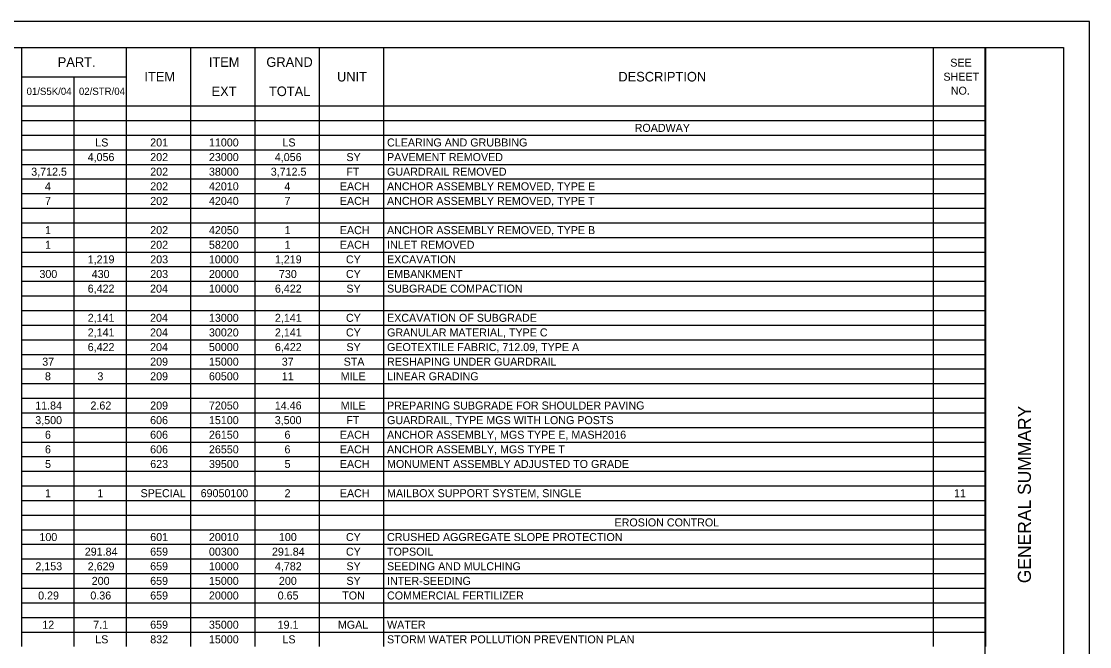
# Model space of a CAD drawing. Extents: x 0 to 34, y 0 to 22.
# Drawn here: x 13.53 to 34, y 10.02 to 22 of the extents above; entities that cross this region are included whole.
import ezdxf

# ---------------------------------------------------------------- set-up
doc = ezdxf.new("R2010")
doc.units = 0
for name, color, linetype in [('SH_Border', 7, 'Continuous'), ('SH_Cut_Line', 7, 'Continuous'), ('SH_Data', 7, 'Continuous'), ('SH_Text', 7, 'Continuous')]:
    doc.layers.add(name, color=color, linetype=linetype)

msp = doc.modelspace()

# ---------------------------------------------------------------- linework, layer by layer
at = {"layer": 'SH_Border'}
msp.add_line((32, 0.5), (32, 21.5), dxfattribs=at)
msp.add_lwpolyline([(1.5, 21.5), (33.5, 21.5), (33.5, 0.5), (1.5, 0.5)], close=True, dxfattribs=at)
at = {"layer": 'SH_Cut_Line'}
msp.add_lwpolyline([(0, 0), (34, 0), (34, 22), (0, 22)], close=True, dxfattribs=at)
at = {"layer": 'SH_Text'}
for p, q in [((13.532, 21.5), (15.537, 21.5)), ((13.532, 21.5), (13.532, 21.22)), ((15.537, 21.5), (32.004, 21.5)), ((15.537, 21.5), (15.537, 21.22)), ((16.771, 21.5), (16.771, 21.22)), ((18.005, 21.5), (18.005, 21.22)), ((19.239, 21.5), (19.239, 21.22)), ((20.473, 21.5), (20.473, 21.22)), ((31.001, 21.5), (31.001, 21.22)), ((32.004, 21.5), (32.004, 21.22)), ((13.532, 21.22), (13.532, 20.94)), ((15.537, 21.22), (15.537, 20.94)), ((16.771, 21.22), (16.771, 20.94)), ((18.005, 21.22), (18.005, 20.94)), ((19.239, 21.22), (19.239, 20.94)), ((20.473, 21.22), (20.473, 20.94)), ((31.001, 21.22), (31.001, 20.94)), ((32.004, 21.22), (32.004, 20.94)), ((13.532, 20.94), (15.537, 20.94)), ((13.532, 20.94), (13.532, 20.66)), ((14.535, 20.94), (14.535, 20.66)), ((15.537, 20.94), (15.537, 20.66)), ((16.771, 20.94), (16.771, 20.66)), ((18.005, 20.94), (18.005, 20.66)), ((19.239, 20.94), (19.239, 20.66)), ((20.473, 20.94), (20.473, 20.66)), ((31.001, 20.94), (31.001, 20.66)), ((32.004, 20.94), (32.004, 20.66)), ((13.532, 20.66), (13.532, 20.38)), ((14.535, 20.66), (14.535, 20.38)), ((15.537, 20.66), (15.537, 20.38)), ((16.771, 20.66), (16.771, 20.38)), ((18.005, 20.66), (18.005, 20.38)), ((19.239, 20.66), (19.239, 20.38)), ((20.473, 20.66), (20.473, 20.38)), ((31.001, 20.66), (31.001, 20.38)), ((32.004, 20.66), (32.004, 20.38)), ((13.532, 20.38), (15.537, 20.38)), ((13.532, 20.38), (13.532, 20.1)), ((14.535, 20.38), (14.535, 20.1)), ((15.537, 20.38), (32.004, 20.38)), ((15.537, 20.38), (15.537, 20.1)), ((16.771, 20.38), (16.771, 20.1)), ((18.005, 20.38), (18.005, 20.1)), ((19.239, 20.38), (19.239, 20.1)), ((20.473, 20.38), (20.473, 20.1)), ((31.001, 20.38), (31.001, 20.1)), ((32.004, 20.38), (32.004, 20.1)), ((13.532, 20.1), (15.537, 20.1)), ((13.532, 20.1), (13.532, 18.7)), ((14.535, 20.1), (14.535, 18.7)), ((15.537, 20.1), (32.004, 20.1)), ((15.537, 20.1), (15.537, 18.7)), ((16.771, 20.1), (16.771, 18.7)), ((18.005, 20.1), (18.005, 18.7)), ((19.239, 20.1), (19.239, 18.7)), ((20.473, 20.1), (20.473, 18.7)), ((31.001, 20.1), (31.001, 18.7)), ((32.004, 20.1), (32.004, 18.7)), ((13.532, 19.82), (15.537, 19.82)), ((15.537, 19.82), (32.004, 19.82)), ((13.532, 19.54), (15.537, 19.54)), ((15.537, 19.54), (32.004, 19.54)), ((13.532, 19.26), (15.537, 19.26)), ((15.537, 19.26), (32.004, 19.26)), ((13.532, 18.98), (15.537, 18.98)), ((15.537, 18.98), (32.004, 18.98)), ((13.532, 18.7), (15.537, 18.7)), ((13.532, 18.7), (13.532, 18.14)), ((14.535, 18.7), (14.535, 18.14)), ((15.537, 18.7), (32.004, 18.7)), ((15.537, 18.7), (15.537, 18.14)), ((16.771, 18.7), (16.771, 18.14)), ((18.005, 18.7), (18.005, 18.14)), ((19.239, 18.7), (19.239, 18.14)), ((20.473, 18.7), (20.473, 18.14)), ((31.001, 18.7), (31.001, 18.14)), ((32.004, 18.7), (32.004, 18.14)), ((13.532, 18.42), (15.537, 18.42)), ((15.537, 18.42), (32.004, 18.42)), ((13.532, 18.14), (15.537, 18.14)), ((13.532, 18.14), (13.532, 17.86)), ((14.535, 18.14), (14.535, 17.86)), ((15.537, 18.14), (32.004, 18.14)), ((15.537, 18.14), (15.537, 17.86)), ((16.771, 18.14), (16.771, 17.86)), ((18.005, 18.14), (18.005, 17.86)), ((19.239, 18.14), (19.239, 17.86)), ((20.473, 18.14), (20.473, 17.86)), ((31.001, 18.14), (31.001, 17.86)), ((32.004, 18.14), (32.004, 17.86)), ((13.532, 17.86), (15.537, 17.86)), ((13.532, 17.86), (13.532, 17.58)), ((14.535, 17.86), (14.535, 17.58)), ((15.537, 17.86), (32.004, 17.86)), ((15.537, 17.86), (15.537, 17.58)), ((16.771, 17.86), (16.771, 17.58)), ((18.005, 17.86), (18.005, 17.58)), ((19.239, 17.86), (19.239, 17.58)), ((20.473, 17.86), (20.473, 17.58)), ((31.001, 17.86), (31.001, 17.58)), ((32.004, 17.86), (32.004, 17.58)), ((13.532, 17.58), (15.537, 17.58)), ((13.532, 17.58), (13.532, 17.3)), ((14.535, 17.58), (14.535, 17.3)), ((15.537, 17.58), (32.004, 17.58)), ((15.537, 17.58), (15.537, 17.3)), ((16.771, 17.58), (16.771, 17.3)), ((18.005, 17.58), (18.005, 17.3)), ((19.239, 17.58), (19.239, 17.3)), ((20.473, 17.58), (20.473, 17.3)), ((31.001, 17.58), (31.001, 17.3)), ((32.004, 17.58), (32.004, 17.3)), ((13.532, 17.3), (15.537, 17.3)), ((13.532, 17.3), (13.532, 17.02)), ((14.535, 17.3), (14.535, 17.02)), ((15.537, 17.3), (32.004, 17.3)), ((15.537, 17.3), (15.537, 17.02)), ((16.771, 17.3), (16.771, 17.02)), ((18.005, 17.3), (18.005, 17.02)), ((19.239, 17.3), (19.239, 17.02)), ((20.473, 17.3), (20.473, 17.02)), ((31.001, 17.3), (31.001, 17.02)), ((32.004, 17.3), (32.004, 17.02)), ((13.532, 17.02), (15.537, 17.02)), ((13.532, 17.02), (13.532, 16.74)), ((14.535, 17.02), (14.535, 16.74)), ((15.537, 17.02), (32.004, 17.02)), ((15.537, 17.02), (15.537, 16.74)), ((16.771, 17.02), (16.771, 16.74)), ((18.005, 17.02), (18.005, 16.74)), ((19.239, 17.02), (19.239, 16.74)), ((20.473, 17.02), (20.473, 16.74)), ((31.001, 17.02), (31.001, 16.74)), ((32.004, 17.02), (32.004, 16.74)), ((13.532, 16.74), (15.537, 16.74)), ((13.532, 16.74), (13.532, 16.18)), ((14.535, 16.74), (14.535, 16.18)), ((15.537, 16.74), (32.004, 16.74)), ((15.537, 16.74), (15.537, 16.18)), ((16.771, 16.74), (16.771, 16.18)), ((18.005, 16.74), (18.005, 16.18)), ((19.239, 16.74), (19.239, 16.18)), ((20.473, 16.74), (20.473, 16.18)), ((31.001, 16.74), (31.001, 16.18)), ((32.004, 16.74), (32.004, 16.18)), ((13.532, 16.46), (15.537, 16.46)), ((15.537, 16.46), (32.004, 16.46)), ((13.532, 16.18), (15.537, 16.18)), ((13.532, 16.18), (13.532, 15.9)), ((14.535, 16.18), (14.535, 15.9)), ((15.537, 16.18), (32.004, 16.18)), ((15.537, 16.18), (15.537, 15.9)), ((16.771, 16.18), (16.771, 15.9)), ((18.005, 16.18), (18.005, 15.9)), ((19.239, 16.18), (19.239, 15.9)), ((20.473, 16.18), (20.473, 15.9)), ((31.001, 16.18), (31.001, 15.9)), ((32.004, 16.18), (32.004, 15.9)), ((13.532, 15.9), (15.537, 15.9)), ((13.532, 15.9), (13.532, 15.62)), ((14.535, 15.9), (14.535, 15.62)), ((15.537, 15.9), (32.004, 15.9)), ((15.537, 15.9), (15.537, 15.62)), ((16.771, 15.9), (16.771, 15.62)), ((18.005, 15.9), (18.005, 15.62)), ((19.239, 15.9), (19.239, 15.62)), ((20.473, 15.9), (20.473, 15.62)), ((31.001, 15.9), (31.001, 15.62)), ((32.004, 15.9), (32.004, 15.62)), ((13.532, 15.62), (15.537, 15.62)), ((13.532, 15.62), (13.532, 15.34)), ((14.535, 15.62), (14.535, 15.34)), ((15.537, 15.62), (32.004, 15.62)), ((15.537, 15.62), (15.537, 15.34)), ((16.771, 15.62), (16.771, 15.34)), ((18.005, 15.62), (18.005, 15.34)), ((19.239, 15.62), (19.239, 15.34)), ((20.473, 15.62), (20.473, 15.34)), ((31.001, 15.62), (31.001, 15.34)), ((32.004, 15.62), (32.004, 15.34)), ((13.532, 15.34), (15.537, 15.34)), ((13.532, 15.34), (13.532, 14.78)), ((14.535, 15.34), (14.535, 14.78)), ((15.537, 15.34), (32.004, 15.34)), ((15.537, 15.34), (15.537, 14.78)), ((16.771, 15.34), (16.771, 14.78)), ((18.005, 15.34), (18.005, 14.78)), ((19.239, 15.34), (19.239, 14.78)), ((20.473, 15.34), (20.473, 14.78)), ((31.001, 15.34), (31.001, 14.78)), ((32.004, 15.34), (32.004, 14.78)), ((13.532, 15.06), (15.537, 15.06)), ((15.537, 15.06), (32.004, 15.06)), ((13.532, 14.78), (15.537, 14.78)), ((13.532, 14.78), (13.532, 14.5)), ((14.535, 14.78), (14.535, 14.5)), ((15.537, 14.78), (32.004, 14.78)), ((15.537, 14.78), (15.537, 14.5)), ((16.771, 14.78), (16.771, 14.5)), ((18.005, 14.78), (18.005, 14.5)), ((19.239, 14.78), (19.239, 14.5)), ((20.473, 14.78), (20.473, 14.5)), ((31.001, 14.78), (31.001, 14.5)), ((32.004, 14.78), (32.004, 14.5)), ((13.532, 14.5), (15.537, 14.5)), ((13.532, 14.5), (13.532, 14.22)), ((14.535, 14.5), (14.535, 14.22)), ((15.537, 14.5), (32.004, 14.5)), ((15.537, 14.5), (15.537, 14.22)), ((16.771, 14.5), (16.771, 14.22)), ((18.005, 14.5), (18.005, 14.22)), ((19.239, 14.5), (19.239, 14.22)), ((20.473, 14.5), (20.473, 14.22)), ((31.001, 14.5), (31.001, 14.22)), ((32.004, 14.5), (32.004, 14.22)), ((13.532, 14.22), (15.537, 14.22)), ((13.532, 14.22), (13.532, 13.94)), ((14.535, 14.22), (14.535, 13.94)), ((15.537, 14.22), (32.004, 14.22)), ((15.537, 14.22), (15.537, 13.94)), ((16.771, 14.22), (16.771, 13.94)), ((18.005, 14.22), (18.005, 13.94)), ((19.239, 14.22), (19.239, 13.94)), ((20.473, 14.22), (20.473, 13.94)), ((31.001, 14.22), (31.001, 13.94)), ((32.004, 14.22), (32.004, 13.94)), ((13.532, 13.94), (15.537, 13.94)), ((13.532, 13.94), (13.532, 11.7)), ((14.535, 13.94), (14.535, 11.7)), ((15.537, 13.94), (32.004, 13.94)), ((15.537, 13.94), (15.537, 11.7)), ((16.771, 13.94), (16.771, 11.7)), ((18.005, 13.94), (18.005, 11.7)), ((19.239, 13.94), (19.239, 11.7)), ((20.473, 13.94), (20.473, 11.7)), ((31.001, 13.94), (31.001, 11.7)), ((32.004, 13.94), (32.004, 11.7)), ((13.532, 13.66), (15.537, 13.66)), ((15.537, 13.66), (32.004, 13.66)), ((13.532, 13.38), (15.537, 13.38)), ((15.537, 13.38), (32.004, 13.38)), ((13.532, 13.1), (15.537, 13.1)), ((15.537, 13.1), (32.004, 13.1)), ((13.532, 12.82), (15.537, 12.82)), ((15.537, 12.82), (32.004, 12.82)), ((13.532, 12.54), (15.537, 12.54)), ((15.537, 12.54), (32.004, 12.54)), ((13.532, 12.26), (15.537, 12.26)), ((15.537, 12.26), (32.004, 12.26)), ((13.532, 11.98), (15.537, 11.98)), ((15.537, 11.98), (32.004, 11.98)), ((13.532, 11.7), (15.537, 11.7)), ((13.532, 11.7), (13.532, 11.42)), ((14.535, 11.7), (14.535, 11.42)), ((15.537, 11.7), (32.004, 11.7)), ((15.537, 11.7), (15.537, 11.42)), ((16.771, 11.7), (16.771, 11.42)), ((18.005, 11.7), (18.005, 11.42)), ((19.239, 11.7), (19.239, 11.42)), ((20.473, 11.7), (20.473, 11.42)), ((31.001, 11.7), (31.001, 11.42)), ((32.004, 11.7), (32.004, 11.42)), ((13.532, 11.42), (15.537, 11.42)), ((13.532, 11.42), (13.532, 10.3)), ((14.535, 11.42), (14.535, 10.3)), ((15.537, 11.42), (32.004, 11.42)), ((15.537, 11.42), (15.537, 10.3)), ((16.771, 11.42), (16.771, 10.3)), ((18.005, 11.42), (18.005, 10.3)), ((19.239, 11.42), (19.239, 10.3)), ((20.473, 11.42), (20.473, 10.3)), ((31.001, 11.42), (31.001, 10.3)), ((32.004, 11.42), (32.004, 10.3)), ((13.532, 11.14), (15.537, 11.14)), ((15.537, 11.14), (32.004, 11.14)), ((13.532, 10.86), (15.537, 10.86)), ((15.537, 10.86), (32.004, 10.86)), ((13.532, 10.58), (15.537, 10.58)), ((15.537, 10.58), (32.004, 10.58)), ((13.532, 10.3), (15.537, 10.3)), ((13.532, 10.3), (13.532, 10.02)), ((14.535, 10.3), (14.535, 10.02)), ((15.537, 10.3), (32.004, 10.3)), ((15.537, 10.3), (15.537, 10.02)), ((16.771, 10.3), (16.771, 10.02)), ((18.005, 10.3), (18.005, 10.02)), ((19.239, 10.3), (19.239, 10.02)), ((20.473, 10.3), (20.473, 10.02)), ((31.001, 10.3), (31.001, 10.02)), ((32.004, 10.3), (32.004, 10.02))]:
    msp.add_line(p, q, dxfattribs=at)

# ---------------------------------------------------------------- texts
at = {"layer": 'SH_Data'}
msp.add_text('GENERAL SUMMARY', height=0.25, rotation=90, dxfattribs=at).set_placement((32.875, 11.235))
at = {"layer": 'SH_Text'}
for s, height, p in [('PART.', 0.184, (14.229, 21.128)), ('ITEM', 0.184, (17.123, 21.128)), ('GRAND', 0.184, (18.226, 21.128)), ('SEE ', 0.1533, (31.33, 21.132)), ('ITEM', 0.184, (15.889, 20.848)), ('UNIT', 0.184, (19.58, 20.848)), ('DESCRIPTION', 0.184, (24.971, 20.848)), ('SHEET ', 0.1533, (31.199, 20.863)), ('01/S5K/04', 0.138, (13.632, 20.591)), ('02/STR/04', 0.138, (14.635, 20.591)), ('EXT', 0.184, (17.176, 20.568)), ('TOTAL', 0.184, (18.276, 20.568)), ('NO.', 0.1533, (31.34, 20.595)), ('ROADWAY', 0.1533, (25.283, 19.883)), ('LS', 0.1533, (14.948, 19.603)), ('201', 0.1533, (16.001, 19.603)), ('11000', 0.1533, (17.126, 19.603)), ('LS', 0.1533, (18.534, 19.603)), ('CLEARING AND GRUBBING', 0.15334, (20.538, 19.603)), ('4,056', 0.1533, (14.802, 19.323)), ('202', 0.1533, (16.001, 19.323)), ('23000', 0.1533, (17.126, 19.323)), ('4,056', 0.1533, (18.388, 19.323)), ('SY', 0.1533, (19.76, 19.323)), ('PAVEMENT REMOVED', 0.15334, (20.538, 19.323)), ('3,712.5', 0.1533, (13.721, 19.043)), ('202', 0.1533, (16.001, 19.043)), ('38000', 0.1533, (17.126, 19.043)), ('3,712.5', 0.1533, (18.31, 19.043)), ('FT', 0.1533, (19.758, 19.043)), ('GUARDRAIL REMOVED', 0.15334, (20.538, 19.043)), ('4', 0.153, (13.983, 18.763)), ('202', 0.1533, (16.001, 18.763)), ('42010', 0.1533, (17.126, 18.763)), ('4', 0.153, (18.572, 18.763)), ('EACH', 0.1533, (19.634, 18.763)), ('ANCHOR ASSEMBLY REMOVED, TYPE E', 0.15334, (20.538, 18.763)), ('7', 0.153, (13.985, 18.483)), ('202', 0.1533, (16.001, 18.483)), ('42040', 0.1533, (17.126, 18.483)), ('7', 0.153, (18.574, 18.483)), ('EACH', 0.1533, (19.634, 18.483)), ('ANCHOR ASSEMBLY REMOVED, TYPE T', 0.15334, (20.538, 18.483)), ('1', 0.153, (13.986, 17.923)), ('202', 0.1533, (16.001, 17.923)), ('42050', 0.1533, (17.126, 17.923)), ('1', 0.153, (18.575, 17.923)), ('EACH', 0.1533, (19.634, 17.923)), ('ANCHOR ASSEMBLY REMOVED, TYPE B', 0.15334, (20.538, 17.923)), ('1', 0.153, (13.986, 17.643)), ('202', 0.1533, (16.001, 17.643)), ('58200', 0.1533, (17.126, 17.643)), ('1', 0.153, (18.575, 17.643)), ('EACH', 0.1533, (19.634, 17.643)), ('INLET REMOVED', 0.15334, (20.538, 17.643)), ('1,219', 0.1533, (14.803, 17.363)), ('203', 0.1533, (16.001, 17.363)), ('10000', 0.1533, (17.126, 17.363)), ('1,219', 0.1533, (18.389, 17.363)), ('CY', 0.1533, (19.751, 17.363)), ('EXCAVATION', 0.1533, (20.538, 17.363)), ('300', 0.1533, (13.878, 17.083)), ('430', 0.1533, (14.88, 17.083)), ('203', 0.1533, (16.001, 17.083)), ('20000', 0.1533, (17.126, 17.083)), ('730', 0.1533, (18.467, 17.083)), ('CY', 0.1533, (19.751, 17.083)), ('EMBANKMENT', 0.1533, (20.538, 17.083)), ('6,422', 0.1533, (14.803, 16.803)), ('204', 0.1533, (15.998, 16.803)), ('10000', 0.1533, (17.126, 16.803)), ('6,422', 0.1533, (18.39, 16.803)), ('SY', 0.1533, (19.76, 16.803)), ('SUBGRADE COMPACTION', 0.15334, (20.538, 16.803)), ('2,141', 0.1533, (14.803, 16.243)), ('204', 0.1533, (15.998, 16.243)), ('13000', 0.1533, (17.126, 16.243)), ('2,141', 0.1533, (18.39, 16.243)), ('CY', 0.1533, (19.751, 16.243)), ('EXCAVATION OF SUBGRADE', 0.15334, (20.538, 16.243)), ('2,141', 0.1533, (14.803, 15.963)), ('204', 0.1533, (15.998, 15.963)), ('30020', 0.1533, (17.126, 15.963)), ('2,141', 0.1533, (18.39, 15.963)), ('CY', 0.1533, (19.751, 15.963)), ('GRANULAR MATERIAL, TYPE C', 0.15334, (20.538, 15.963)), ('6,422', 0.1533, (14.803, 15.683)), ('204', 0.1533, (15.998, 15.683)), ('50000', 0.1533, (17.126, 15.683)), ('6,422', 0.1533, (18.39, 15.683)), ('SY', 0.1533, (19.76, 15.683)), ('GEOTEXTILE FABRIC, 712.09, TYPE A', 0.15334, (20.538, 15.683)), ('37', 0.1533, (13.932, 15.403)), ('209', 0.1533, (16, 15.403)), ('15000', 0.1533, (17.126, 15.403)), ('37', 0.1533, (18.521, 15.403)), ('STA', 0.1533, (19.707, 15.403)), ('RESHAPING UNDER GUARDRAIL', 0.15334, (20.538, 15.403)), ('8', 0.153, (13.984, 15.123)), ('3', 0.153, (14.989, 15.123)), ('209', 0.1533, (16, 15.123)), ('60500', 0.1533, (17.126, 15.123)), ('11', 0.1533, (18.522, 15.123)), ('MILE', 0.1533, (19.651, 15.123)), ('LINEAR GRADING', 0.15334, (20.538, 15.123)), ('11.84', 0.1533, (13.797, 14.563)), ('2.62', 0.1533, (14.856, 14.563)), ('209', 0.1533, (16, 14.563)), ('72050', 0.1533, (17.126, 14.563)), ('14.46', 0.1533, (18.388, 14.563)), ('MILE', 0.1533, (19.651, 14.563)), ('PREPARING SUBGRADE FOR SHOULDER PAVING', 0.15334, (20.538, 14.563)), ('3,500', 0.1533, (13.798, 14.283)), ('606', 0.1533, (15.999, 14.283)), ('15100', 0.1533, (17.126, 14.283)), ('3,500', 0.1533, (18.387, 14.283)), ('FT', 0.1533, (19.758, 14.283)), ('GUARDRAIL, TYPE MGS WITH LONG POSTS', 0.15334, (20.538, 14.283)), ('6', 0.153, (13.984, 14.003)), ('606', 0.1533, (15.999, 14.003)), ('26150', 0.1533, (17.126, 14.003)), ('6', 0.153, (18.573, 14.003)), ('EACH', 0.1533, (19.634, 14.003)), ('ANCHOR ASSEMBLY, MGS TYPE E, MASH2016', 0.15334, (20.538, 14.003)), ('6', 0.153, (13.984, 13.723)), ('606', 0.1533, (15.999, 13.723)), ('26550', 0.1533, (17.126, 13.723)), ('6', 0.153, (18.573, 13.723)), ('EACH', 0.1533, (19.634, 13.723)), ('ANCHOR ASSEMBLY, MGS TYPE T', 0.15334, (20.538, 13.723)), ('5', 0.153, (13.986, 13.443)), ('623', 0.1533, (16.001, 13.443)), ('39500', 0.1533, (17.126, 13.443)), ('5', 0.153, (18.575, 13.443)), ('EACH', 0.1533, (19.634, 13.443)), ('MONUMENT ASSEMBLY ADJUSTED TO GRADE', 0.15334, (20.538, 13.443)), ('1', 0.153, (13.986, 12.883)), ('1', 0.153, (14.989, 12.883)), ('SPECIAL', 0.1533, (15.816, 12.883)), ('69050100', 0.1533, (16.967, 12.883)), ('2', 0.153, (18.575, 12.883)), ('EACH', 0.1533, (19.634, 12.883)), ('MAILBOX SUPPORT SYSTEM, SINGLE', 0.15334, (20.538, 12.883)), ('11', 0.1533, (31.402, 12.883)), ('EROSION CONTROL', 0.15334, (24.897, 12.323)), ('100', 0.1533, (13.878, 12.043)), ('601', 0.1533, (16.001, 12.043)), ('20010', 0.1533, (17.126, 12.043)), ('100', 0.1533, (18.467, 12.043)), ('CY', 0.1533, (19.751, 12.043)), ('CRUSHED AGGREGATE SLOPE PROTECTION', 0.15334, (20.538, 12.043)), ('291.84', 0.1533, (14.747, 11.763)), ('659', 0.1533, (16, 11.763)), ('00300', 0.1533, (17.126, 11.763)), ('291.84', 0.1533, (18.333, 11.763)), ('CY', 0.1533, (19.751, 11.763)), ('TOPSOIL', 0.1533, (20.538, 11.763)), ('2,153', 0.1533, (13.801, 11.483)), ('2,629', 0.1533, (14.803, 11.483)), ('659', 0.1533, (16, 11.483)), ('10000', 0.1533, (17.126, 11.483)), ('4,782', 0.1533, (18.39, 11.483)), ('SY', 0.1533, (19.76, 11.483)), ('SEEDING AND MULCHING', 0.15334, (20.538, 11.483)), ('200', 0.1533, (14.88, 11.203)), ('659', 0.1533, (16, 11.203)), ('15000', 0.1533, (17.126, 11.203)), ('200', 0.1533, (18.467, 11.203)), ('SY', 0.1533, (19.76, 11.203)), ('INTER-SEEDING', 0.15334, (20.538, 11.203)), ('0.29', 0.1533, (13.853, 10.923)), ('0.36', 0.1533, (14.854, 10.923)), ('659', 0.1533, (16, 10.923)), ('20000', 0.1533, (17.126, 10.923)), ('0.65', 0.1533, (18.443, 10.923)), ('TON', 0.1533, (19.68, 10.923)), ('COMMERCIAL FERTILIZER', 0.15334, (20.538, 10.923)), ('12', 0.1533, (13.933, 10.363)), ('7.1', 0.1533, (14.909, 10.363)), ('659', 0.1533, (16, 10.363)), ('35000', 0.1533, (17.126, 10.363)), ('19.1', 0.1533, (18.442, 10.363)), ('MGAL', 0.1533, (19.597, 10.363)), ('WATER', 0.1533, (20.538, 10.363)), ('LS', 0.1533, (14.948, 10.083)), ('832', 0.1533, (16.001, 10.083)), ('15000', 0.1533, (17.126, 10.083)), ('LS', 0.1533, (18.534, 10.083)), ('STORM WATER POLLUTION PREVENTION PLAN', 0.15334, (20.538, 10.083))]:
    msp.add_text(s, height=height, dxfattribs=at).set_placement(p)

doc.saveas('drawing.dxf')
